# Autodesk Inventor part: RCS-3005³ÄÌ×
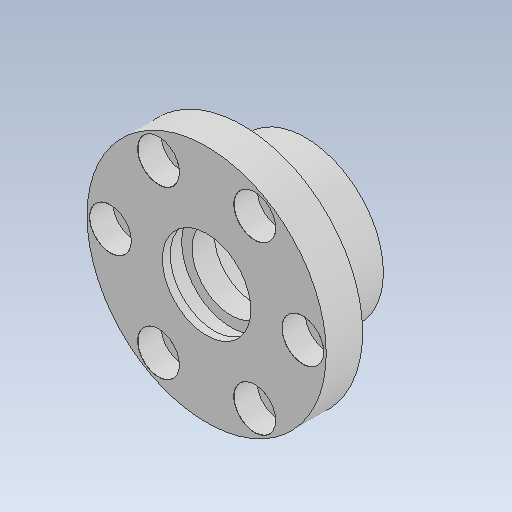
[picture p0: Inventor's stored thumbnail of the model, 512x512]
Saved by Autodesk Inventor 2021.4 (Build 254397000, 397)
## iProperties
Created: 2019-12
Part Number: RCS-3005³ÄÌ×
Material: Ogólny
Document SubType Name: Modeling
Designer: user
Density: 1 g/cm^3
Appearance: Domyślna
Author: user
Revision Number: ÈÎºÎ
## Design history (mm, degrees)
feature "ÇÐ³ý-À­Éì2"
node "Bryła1"
